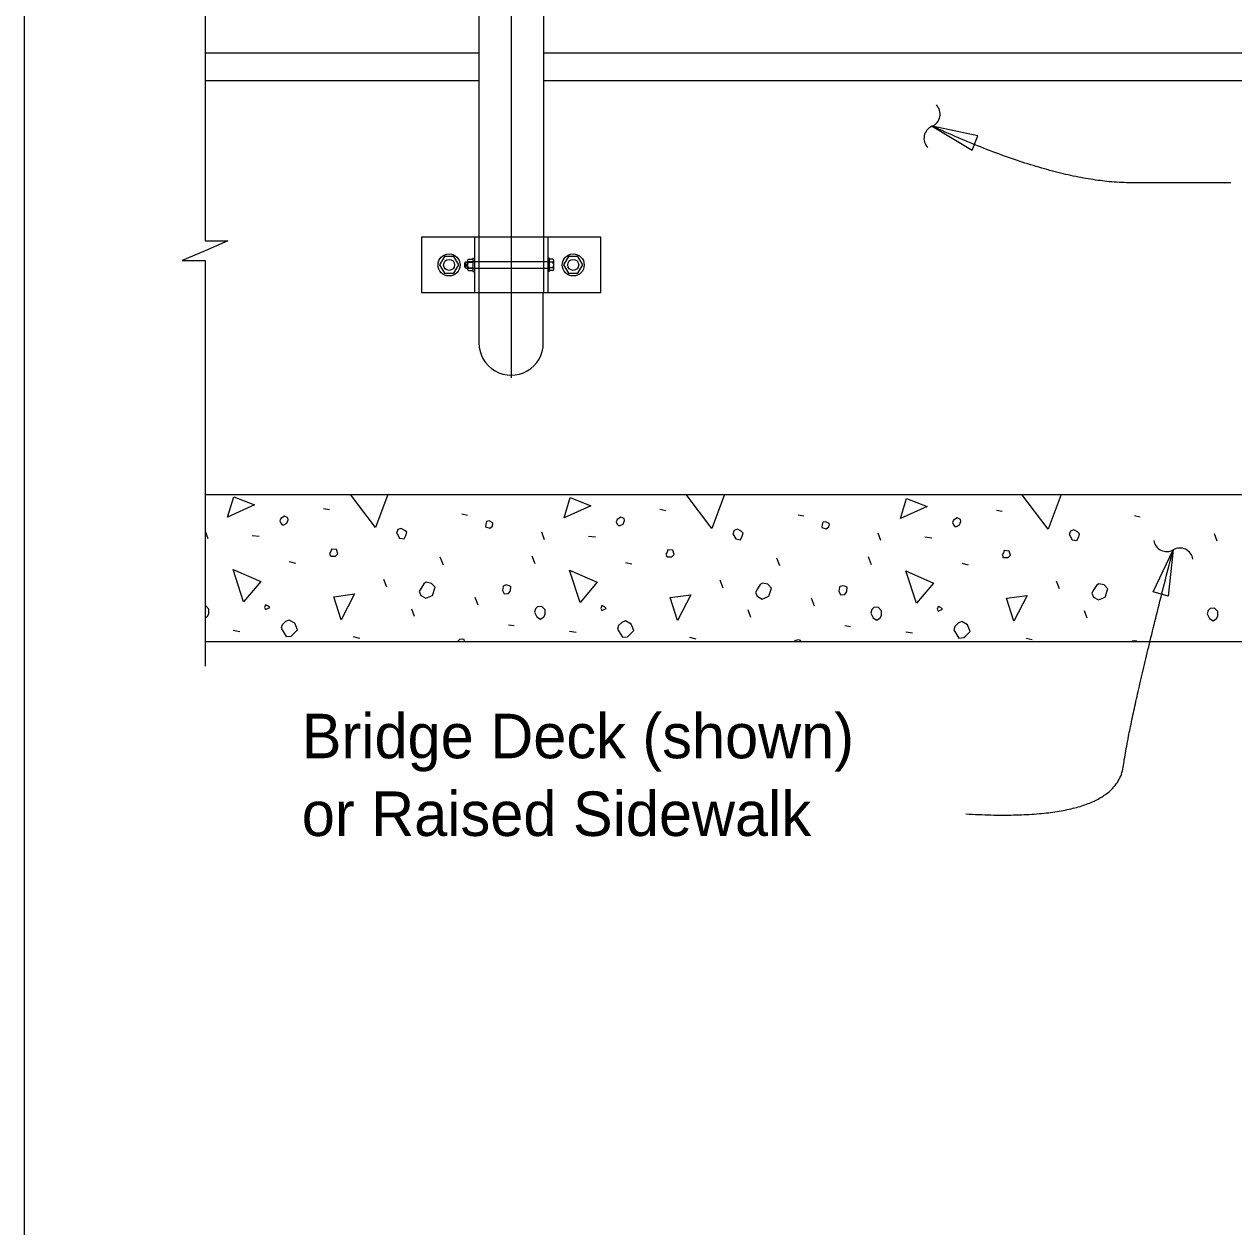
# Model space of a CAD drawing. Extents: x 0 to 72.1, y -7 to 30.
# Drawn here: x 0.02 to 5.5, y 12.87 to 18.32 of the extents above; entities that cross this region are included whole.
import ezdxf

# ---------------------------------------------------------------- set-up
doc = ezdxf.new("R2010")
doc.units = 0
for name, color, linetype in [('ActivePts-ConstElements', 7, 'Continuous'), ('AdhocPoint_dp', 7, 'Continuous'), ('Border', 7, 'Continuous'), ('Patterning', 7, 'Continuous'), ('PlotBorder_dp', 7, 'Continuous'), ('SheetBorder_dp', 7, 'Continuous'), ('TextMisc', 7, 'Continuous')]:
    doc.layers.add(name, color=color, linetype=linetype)

msp = doc.modelspace()

# ---------------------------------------------------------------- linework, layer by layer
at = {"layer": 'ActivePts-ConstElements'}
msp.add_lwpolyline([(0.016, 2.0538), (41.2266, 2.0538), (41.2266, 28.0138), (0.016, 28.0138)], close=True, dxfattribs=at)
at = {"layer": 'AdhocPoint_dp'}
for p, q in [((2.0146, 17.2229), (2.0146, 17.235)), ((2.0203, 17.2229), (2.0203, 17.235)), ((1.3727, 16.1263), (1.3992, 16.121)), ((2.8965, 16.1228), (2.923, 16.1175)), ((4.4203, 16.1192), (4.4468, 16.1139)), ((1.9985, 16.1015), (2.025, 16.0962)), ((3.5223, 16.098), (3.5488, 16.0927)), ((5.0461, 16.0945), (5.0726, 16.0892)), ((0.8494, 15.9884), (0.837, 16.022)), ((1.0492, 16.0043), (1.081, 16.0008)), ((2.3732, 15.9849), (2.3609, 16.0185)), ((3.897, 15.9813), (3.8847, 16.0149)), ((5.4209, 15.9778), (5.4085, 16.0114)), ((2.573, 16.0008), (2.6048, 15.9972)), ((4.0968, 15.9972), (4.1286, 15.9937)), ((1.9154, 15.87), (1.9012, 15.9053)), ((2.3308, 15.8753), (2.3167, 15.9106)), ((3.4392, 15.8664), (3.4251, 15.9018)), ((3.8546, 15.8717), (3.8405, 15.9071)), ((1.2171, 15.8859), (1.2454, 15.8788)), ((2.7409, 15.8823), (2.7692, 15.8753)), ((4.2647, 15.8788), (4.293, 15.8717)), ((1.6591, 15.7692), (1.6449, 15.8046)), ((3.1829, 15.7657), (3.1687, 15.801)), ((4.7067, 15.7621), (4.6925, 15.7975)), ((2.0727, 15.6879), (2.0586, 15.7232)), ((3.5965, 15.6844), (3.5824, 15.7197)), ((1.7846, 15.6366), (1.7722, 15.6702)), ((3.3084, 15.6331), (3.296, 15.6667)), ((4.8322, 15.6296), (4.8198, 15.6631)), ((0.9626, 15.5748), (0.9926, 15.5694)), ((2.2106, 15.5995), (2.2353, 15.596)), ((2.4864, 15.5712), (2.5164, 15.5659)), ((3.7344, 15.596), (3.7592, 15.5924)), ((4.0102, 15.5677), (4.0402, 15.5624)), ((1.507, 15.5465), (1.5353, 15.5394)), ((3.0308, 15.5429), (3.0591, 15.5359)), ((4.5547, 15.5394), (4.5829, 15.5323))]:
    msp.add_line(p, q, dxfattribs=at)
for points in [[(0.9378, 16.0874), (0.9661, 16.1793), (1.0598, 16.1422), (0.9378, 16.0874)], [(1.6078, 16.0397), (1.4936, 16.1899)], [(1.6639, 16.1899), (1.6078, 16.0397)], [(2.4616, 16.0839), (2.4899, 16.1758), (2.5836, 16.1387), (2.4616, 16.0839)], [(3.1316, 16.0361), (3.0147, 16.1899)], [(3.1891, 16.1899), (3.1316, 16.0361)], [(3.9854, 16.0803), (4.0137, 16.1723), (4.1074, 16.1351), (3.9854, 16.0803)], [(4.6554, 16.0326), (4.5358, 16.1899)], [(4.7142, 16.1899), (4.6554, 16.0326)], [(1.1853, 16.052), (1.1924, 16.052), (1.2065, 16.0591), (1.2118, 16.075), (1.21, 16.0839), (1.1959, 16.0909), (1.1782, 16.0803), (1.1747, 16.0697), (1.1782, 16.0591), (1.1853, 16.052)], [(2.1063, 16.0432), (2.1257, 16.0379), (2.1381, 16.0467), (2.1399, 16.0591), (2.1364, 16.0627), (2.1222, 16.0697), (2.1098, 16.068), (2.1081, 16.0556), (2.1063, 16.0432)], [(2.7091, 16.0485), (2.7162, 16.0485), (2.7303, 16.0556), (2.7356, 16.0715), (2.7339, 16.0803), (2.7197, 16.0874), (2.702, 16.0768), (2.6985, 16.0662), (2.702, 16.0556), (2.7091, 16.0485)], [(3.6301, 16.0397), (3.6496, 16.0344), (3.6619, 16.0432), (3.6637, 16.0556), (3.6602, 16.0591), (3.646, 16.0662), (3.6337, 16.0644), (3.6319, 16.052), (3.6301, 16.0397)], [(4.2329, 16.045), (4.24, 16.045), (4.2541, 16.052), (4.2594, 16.068), (4.2577, 16.0768), (4.2435, 16.0839), (4.2259, 16.0733), (4.2223, 16.0627), (4.2259, 16.052), (4.2329, 16.045)], [(1.7068, 16.0079), (1.7156, 15.9919), (1.7368, 15.9884), (1.7457, 16.0043), (1.7492, 16.0185), (1.7404, 16.0273), (1.7245, 16.0361), (1.7086, 16.0308), (1.7033, 16.0149), (1.7068, 16.0079)], [(3.2306, 16.0043), (3.2394, 15.9884), (3.2607, 15.9849), (3.2695, 16.0008), (3.273, 16.0149), (3.2642, 16.0238), (3.2483, 16.0326), (3.2324, 16.0273), (3.2271, 16.0114), (3.2306, 16.0043)], [(4.7544, 16.0008), (4.7633, 15.9849), (4.7845, 15.9813), (4.7933, 15.9972), (4.7968, 16.0114), (4.788, 16.0202), (4.7721, 16.0291), (4.7562, 16.0238), (4.7509, 16.0079), (4.7544, 16.0008)], [(1.4045, 15.9106), (1.4257, 15.9106), (1.4363, 15.9212), (1.431, 15.9407), (1.408, 15.9424), (1.4045, 15.9318), (1.3992, 15.923), (1.4045, 15.9106), (1.401, 15.9142)], [(2.9283, 15.9071), (2.9495, 15.9071), (2.9601, 15.9177), (2.9548, 15.9371), (2.9318, 15.9389), (2.9283, 15.9283), (2.923, 15.9195), (2.9283, 15.9071), (2.9248, 15.9106)], [(4.4521, 15.9036), (4.4733, 15.9036), (4.4839, 15.9142), (4.4786, 15.9336), (4.4557, 15.9354), (4.4521, 15.9248), (4.4468, 15.9159), (4.4521, 15.9036), (4.4486, 15.9071)], [(1.0103, 15.7038), (0.9626, 15.8505), (1.0881, 15.7957), (1.0103, 15.7038)], [(2.5341, 15.7003), (2.4864, 15.847), (2.6119, 15.7922), (2.5341, 15.7003)], [(4.0579, 15.6967), (4.0102, 15.8435), (4.1357, 15.7887), (4.0579, 15.6967)], [(1.8129, 15.7321), (1.8358, 15.7197), (1.8659, 15.7321), (1.8783, 15.7692), (1.8606, 15.7869), (1.8376, 15.7922), (1.827, 15.7851), (1.8146, 15.7657), (1.8058, 15.7498), (1.8129, 15.7321)], [(3.3367, 15.7285), (3.3596, 15.7162), (3.3897, 15.7285), (3.4021, 15.7657), (3.3844, 15.7833), (3.3614, 15.7887), (3.3508, 15.7816), (3.3384, 15.7621), (3.3296, 15.7462), (3.3367, 15.7285)], [(4.8605, 15.725), (4.8835, 15.7126), (4.9135, 15.725), (4.9259, 15.7621), (4.9082, 15.7798), (4.8852, 15.7851), (4.8746, 15.778), (4.8622, 15.7586), (4.8534, 15.7427), (4.8605, 15.725)], [(1.4522, 15.6225), (1.4186, 15.7268), (1.5123, 15.7392), (1.4522, 15.6225)], [(2.1823, 15.7551), (2.1912, 15.7392), (2.2106, 15.7409), (2.2194, 15.7533), (2.2212, 15.7727), (2.2088, 15.778), (2.2, 15.7798), (2.1894, 15.7763), (2.1859, 15.7727), (2.1823, 15.7551)], [(2.976, 15.6189), (2.9425, 15.7232), (3.0361, 15.7356), (2.976, 15.6189)], [(3.7061, 15.7515), (3.715, 15.7356), (3.7344, 15.7374), (3.7433, 15.7498), (3.745, 15.7692), (3.7326, 15.7745), (3.7238, 15.7763), (3.7132, 15.7727), (3.7097, 15.7692), (3.7061, 15.7515)], [(4.4999, 15.6154), (4.4663, 15.7197), (4.56, 15.7321), (4.4999, 15.6154)], [(0.8353, 15.6304), (0.8459, 15.6384), (0.853, 15.649), (0.853, 15.6702), (0.837, 15.6861), (0.8353, 15.686)], [(1.1093, 15.6684), (1.1287, 15.6773), (1.1217, 15.6844), (1.1093, 15.6897), (1.104, 15.6773), (1.1093, 15.6684)], [(2.3273, 15.6561), (2.3379, 15.6349), (2.3556, 15.6242), (2.3697, 15.6349), (2.3768, 15.6455), (2.3768, 15.6667), (2.3609, 15.6826), (2.3414, 15.6808), (2.3326, 15.672), (2.3273, 15.6561)], [(2.6331, 15.6649), (2.6525, 15.6737), (2.6455, 15.6808), (2.6331, 15.6861), (2.6278, 15.6737), (2.6331, 15.6649)], [(3.8511, 15.6525), (3.8617, 15.6313), (3.8794, 15.6207), (3.8935, 15.6313), (3.9006, 15.6419), (3.9006, 15.6631), (3.8847, 15.679), (3.8652, 15.6773), (3.8564, 15.6684), (3.8511, 15.6525)], [(4.1569, 15.6614), (4.1764, 15.6702), (4.1693, 15.6773), (4.1569, 15.6826), (4.1516, 15.6702), (4.1569, 15.6614)], [(5.3749, 15.649), (5.3855, 15.6278), (5.4032, 15.6172), (5.4173, 15.6278), (5.4244, 15.6384), (5.4244, 15.6596), (5.4085, 15.6755), (5.389, 15.6737), (5.3802, 15.6649), (5.3749, 15.649)], [(1.18, 15.5836), (1.203, 15.5465), (1.226, 15.5482), (1.2348, 15.5571), (1.2542, 15.5765), (1.2419, 15.6066), (1.2171, 15.6207), (1.1994, 15.6136), (1.1853, 15.5995), (1.18, 15.5836)], [(2.7038, 15.5801), (2.7268, 15.5429), (2.7498, 15.5447), (2.7586, 15.5535), (2.7781, 15.573), (2.7657, 15.603), (2.7409, 15.6172), (2.7233, 15.6101), (2.7091, 15.596), (2.7038, 15.5801)], [(4.2276, 15.5765), (4.2506, 15.5394), (4.2736, 15.5412), (4.2824, 15.55), (4.3019, 15.5694), (4.2895, 15.5995), (4.2647, 15.6136), (4.2471, 15.6066), (4.2329, 15.5924), (4.2276, 15.5765)], [(2.0109, 15.5233), (2.0091, 15.5323), (2.0002, 15.5341), (1.9879, 15.5323), (1.9788, 15.5233)], [(3.534, 15.5233), (3.5329, 15.5288), (3.5241, 15.5306), (3.5117, 15.5288), (3.5062, 15.5233)], [(5.0571, 15.5233), (5.0567, 15.5253), (5.0479, 15.527), (5.0355, 15.5253), (5.0335, 15.5233)]]:
    msp.add_lwpolyline(points, dxfattribs=at)
at = {"layer": 'Border'}
msp.add_lwpolyline([(0.8354, 19.19), (0.8354, 17.3392), (0.9387, 17.3392), (0.8354, 17.2942), (0.7321, 17.2492), (0.8354, 17.2492), (0.8354, 15.4114)], dxfattribs=at)
for points in [[(4.1293, 17.8584), (4.3102, 17.7494), (4.3361, 17.815)], [(5.2211, 15.9394), (5.1989, 15.7293), (5.1309, 15.7484)]]:
    msp.add_lwpolyline(points, close=True, dxfattribs=at)
for centre, start, end in [((4.106, 17.9127), 292.7091, 44.4364), ((4.152, 17.8027), 112.7091, 224.4364), ((5.192, 15.9906), 188.4294, 300.1567), ((5.2519, 15.8876), 8.4294, 120.1567)]:
    msp.add_arc(centre, 0.0596, start, end, dxfattribs=at)
for points in [[(5.483, 17.6014), (5.3863, 17.6014), (4.6869, 17.6014), (4.1292, 17.8584)], [(4.2826, 14.7427), (4.9583, 14.7033), (5.0321, 15.2106), (5.2212, 15.9393)]]:
    msp.add_open_spline(points, degree=2, dxfattribs=at)
at = {"layer": 'Patterning'}
for p, q in [((2.0763, 17.3548), (2.0763, 17.1048)), ((2.368, 17.3548), (2.368, 17.1048)), ((2.3889, 17.2444), (2.024, 17.2444)), ((2.024, 17.2145), (2.3889, 17.2145))]:
    msp.add_line(p, q, dxfattribs=at)
at = {"layer": 'PlotBorder_dp'}
for p, q in [((2.0763, 18.6048), (2.0763, 17.3548)), ((2.368, 18.6048), (2.368, 17.3548)), ((2.6282, 17.3548), (1.8162, 17.3548)), ((1.8162, 17.3548), (1.8162, 17.1048)), ((2.0555, 17.3548), (2.0555, 17.1048)), ((2.3888, 17.3548), (2.3888, 17.1048)), ((2.6282, 17.1048), (2.6282, 17.3548)), ((2.0118, 17.2378), (2.0174, 17.2444)), ((2.0118, 17.2201), (2.0118, 17.2378)), ((2.0118, 17.2201), (2.0174, 17.2145)), ((2.0174, 17.2444), (2.024, 17.2444)), ((2.0174, 17.2145), (2.0174, 17.2444)), ((2.0174, 17.2145), (2.024, 17.2145)), ((2.024, 17.2477), (2.024, 17.212)), ((2.0287, 17.2428), (2.049, 17.2428)), ((2.0287, 17.2169), (2.049, 17.2169)), ((2.0289, 17.2558), (2.049, 17.2558)), ((2.049, 17.2601), (2.049, 17.1995)), ((2.049, 17.2601), (2.0555, 17.2601)), ((2.049, 17.2558), (2.049, 17.2039)), ((2.3951, 17.2601), (2.3891, 17.2601)), ((2.3951, 17.2601), (2.3951, 17.1995)), ((2.4098, 17.2558), (2.3951, 17.2558)), ((2.41, 17.2428), (2.3951, 17.2428)), ((2.41, 17.2168), (2.3951, 17.2168)), ((2.4149, 17.2104), (2.4149, 17.2493)), ((2.029, 17.2039), (2.049, 17.2039)), ((2.049, 17.1995), (2.0555, 17.1995)), ((2.3951, 17.1995), (2.3891, 17.1995)), ((2.4098, 17.2038), (2.3951, 17.2038)), ((1.8162, 17.1048), (2.6282, 17.1048)), ((2.0763, 17.1048), (2.0763, 16.8757)), ((2.3679, 16.8757), (2.3679, 17.1048))]:
    msp.add_line(p, q, dxfattribs=at)
for points in [[(1.9629, 17.2674), (1.9195, 17.2674), (1.8978, 17.2298), (1.9195, 17.1923), (1.9629, 17.1923), (1.9845, 17.2298)], [(2.5248, 17.2674), (2.4815, 17.2674), (2.4598, 17.2298), (2.4815, 17.1923), (2.5248, 17.1923), (2.5465, 17.2298)]]:
    msp.add_lwpolyline(points, close=True, dxfattribs=at)
for centre, radius in [((1.9412, 17.2298), 0.05), ((2.5032, 17.2298), 0.05), ((1.9412, 17.2298), 0.025), ((2.5032, 17.2298), 0.025)]:
    msp.add_circle(centre, radius, dxfattribs=at)
for centre, radius, start, end in [((2.0305, 17.2493), 0.00674, 104.4891, 254.1889), ((2.0434, 17.2298), 0.0196, 138.628, 221.372), ((2.0305, 17.2104), 0.00673, 105.7823, 255.5404), ((2.4081, 17.2493), 0.00673, 285.7823, 75.5404), ((2.4081, 17.2104), 0.00674, 284.4891, 74.1889), ((2.3952, 17.2298), 0.0196, 318.628, 41.372)]:
    msp.add_arc(centre, radius, start, end, dxfattribs=at)
msp.add_ellipse((2.2222, 16.8757), major_axis=(0, 0.1458), ratio=0.999499, start_param=1.570796, end_param=4.712389, dxfattribs=at)
at = {"layer": 'SheetBorder_dp'}
msp.add_line((2.2222, 27.5581), (2.2222, 16.7178), dxfattribs=at)
at = {"layer": 'TextMisc'}
for p, q in [((0.8353, 18.1899), (2.0763, 18.1899)), ((2.368, 18.1899), (12.0764, 18.1899)), ((0.8353, 18.0649), (2.0763, 18.0649)), ((2.368, 18.0649), (12.0764, 18.0649)), ((0.8353, 16.1899), (23.6092, 16.1899)), ((0.8353, 15.5233), (23.6092, 15.5233))]:
    msp.add_line(p, q, dxfattribs=at)

# ---------------------------------------------------------------- texts
at = {"layer": 'Border'}
for s, p in [('Bridge Deck (shown)', (1.2735, 14.9948)), ('or Raised Sidewalk', (1.2735, 14.6428))]:
    msp.add_text(s, height=0.2016, dxfattribs=at).set_placement(p)

doc.saveas('drawing.dxf')
